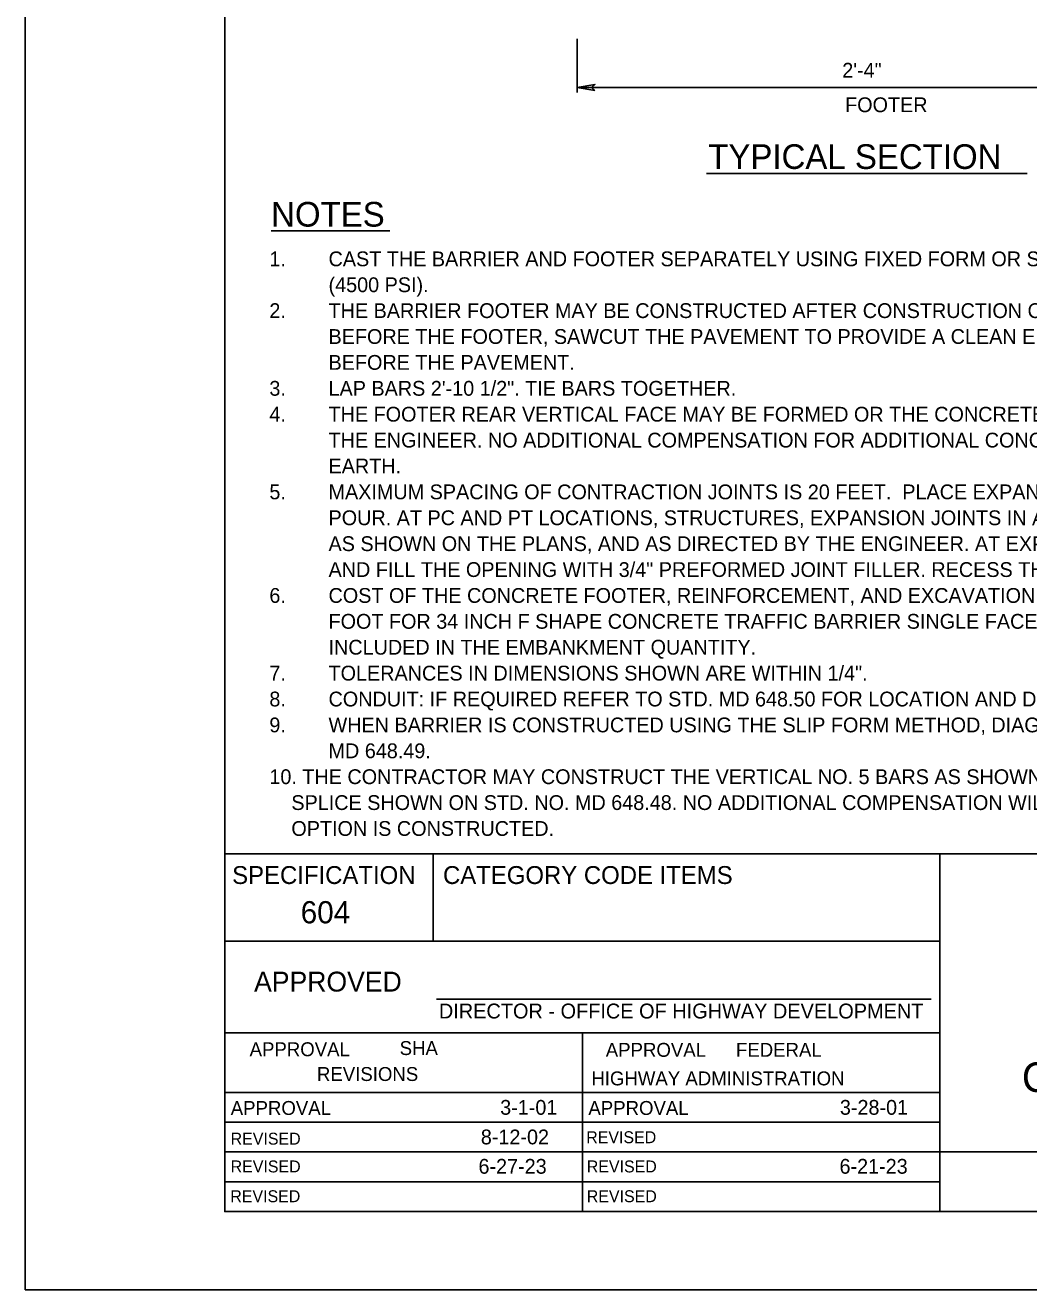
# Model space of a CAD drawing. Extents: x -32.9 to -15.8, y -6.5 to 4.5.
# Drawn here: x -24.32 to -20.25, y -6.5 to -1.37 of the extents above; entities that cross this region are included whole.
import ezdxf

# ---------------------------------------------------------------- set-up
doc = ezdxf.new("R2010")
doc.units = 0
for name, color, linetype in [('BORD-LINE', 7, 'Continuous'), ('DETL-DIMS', 7, 'Continuous'), ('Level 10', 7, 'Continuous'), ('Level 12', 7, 'Continuous'), ('Level 13', 7, 'Continuous'), ('TTLB-TEXT', 7, 'Continuous'), ('USER-CLIP', 7, 'Continuous')]:
    doc.layers.add(name, color=color, linetype=linetype)

msp = doc.modelspace()

# ---------------------------------------------------------------- linework, layer by layer
at = {"layer": 'BORD-LINE'}
for p, q in [((-20.6138, -4.729), (-23.5151, -4.729)), ((-22.6689, -5.0837), (-22.6689, -4.729)), ((-20.6138, -6.1798), (-20.6138, -4.729)), ((-16.1409, -4.729), (-20.6138, -4.729)), ((-23.5151, -5.0837), (-20.6138, -5.0837)), ((-22.6559, -5.3188), (-20.649, -5.3188)), ((-23.5151, -5.4544), (-22.6689, -5.4544)), ((-23.5151, -6.1798), (-23.5151, -5.4544)), ((-23.5151, -5.4544), (-20.6138, -5.4544)), ((-22.0644, -5.4544), (-22.0644, -6.1798)), ((-23.5151, -5.6962), (-20.6138, -5.6962)), ((-23.5151, -5.8171), (-20.6138, -5.8171)), ((-23.5151, -5.938), (-20.6138, -5.938)), ((-20.6138, -5.938), (-16.1409, -5.938)), ((-23.5151, -6.0589), (-20.6138, -6.0589)), ((-22.6689, -6.0589), (-20.6138, -6.0589))]:
    msp.add_line(p, q, dxfattribs=at)
msp.add_lwpolyline([(-23.5151, 4.1733), (-16.1409, 4.1733), (-16.1409, -6.1798), (-23.5151, -6.1798)], close=True, dxfattribs=at)
at = {"layer": 'DETL-DIMS'}
for p, q in [((-22.0848, -1.6207), (-22.0132, -1.608)), ((-22.0848, -1.6207), (-22.0133, -1.6332)), ((-22.0268, -1.6207), (-22.0132, -1.608)), ((-22.0133, -1.6332), (-22.0268, -1.6207))]:
    msp.add_line(p, q, dxfattribs=at)
msp.add_lwpolyline([(-22.0133, -1.6332), (-22.0848, -1.6207), (-22.0132, -1.608), (-22.0268, -1.6207)], close=True, dxfattribs=at)
at = {"layer": 'Level 10'}
for p, q in [((-22.0848, -1.4234), (-22.0848, -1.6415)), ((-19.752, -1.6207), (-22.0848, -1.6207))]:
    msp.add_line(p, q, dxfattribs=at)
at = {"layer": 'Level 12'}
msp.add_line((-21.5603, -1.9696), (-20.2595, -1.9696), dxfattribs=at)
at = {"layer": 'Level 13'}
msp.add_line((-23.3268, -2.2021), (-22.8451, -2.2021), dxfattribs=at)
at = {"layer": 'USER-CLIP'}
msp.add_lwpolyline([(-15.824, 4.5033), (-24.324, 4.5033), (-24.324, -6.4967), (-15.824, -6.4967)], close=True, dxfattribs=at)

# ---------------------------------------------------------------- texts
at = {"layer": 'Level 12'}
for s, height, p in [('2\'-4"', 0.06001, (-21.0101, -1.5807)), ('FOOTER', 0.06001, (-20.9986, -1.7207)), ('TYPICAL SECTION', 0.100016, (-21.5536, -1.951))]:
    msp.add_text(s, height=height, dxfattribs=at).set_placement(p)
at = {"layer": 'Level 13'}
for s, height, p in [('NOTES', 0.10002, (-23.3268, -2.1849)), ('1.', 0.06001, (-23.3339, -2.3457)), ('CAST THE BARRIER AND FOOTER SEPARATELY USING FIXED FORM OR SLIP FORM CONSTRUCTION WITH CONCRETE MIX NO.6 ', 0.0600095, (-23.0939, -2.3457)), ('(4500 PSI).', 0.06001, (-23.0939, -2.4507)), ('2.', 0.06001, (-23.3339, -2.5557)), ('THE BARRIER FOOTER MAY BE CONSTRUCTED AFTER CONSTRUCTION OF THE PAVEMENT. IF FLEXIBLE PAVEMENT IS CONSTRUCTED ', 0.0600095, (-23.0939, -2.5557)), ('BEFORE THE FOOTER, SAWCUT THE PAVEMENT TO PROVIDE A CLEAN EDGE. REMOVE FOOTER FORMS IF THE FOOTER IS CONSTRUCTED ', 0.0600095, (-23.0939, -2.6607)), ('BEFORE THE PAVEMENT.', 0.06001, (-23.0939, -2.7657)), ('3.', 0.06001, (-23.3339, -2.8708)), ('LAP BARS 2\'-10 1/2". TIE BARS TOGETHER.', 0.06001, (-23.0939, -2.8708)), ('4.', 0.06001, (-23.3339, -2.9758)), ('THE FOOTER REAR VERTICAL FACE MAY BE FORMED OR THE CONCRETE PLACED AGAINST THE VERTICAL EARTH SIDE IF APPROVED BY ', 0.0600095, (-23.0939, -2.9758)), ('THE ENGINEER. NO ADDITIONAL COMPENSATION FOR ADDITIONAL CONCRETE WILL BE PAID IF CONCRETE IS PLACED AGAINST THE ', 0.0600095, (-23.0939, -3.0808)), ('EARTH.', 0.06001, (-23.0939, -3.1858)), ('5.', 0.06001, (-23.3339, -3.2908)), ('MAXIMUM SPACING OF CONTRACTION JOINTS IS 20 FEET.  PLACE EXPANSION JOINTS IN THE BARRIER AND FOOTER AT THE END OF ', 0.0600095, (-23.0939, -3.2908)), ('POUR. AT PC AND PT LOCATIONS, STRUCTURES, EXPANSION JOINTS IN ABUTTING CONCRETE AND UNDERLYING CONCRETE. LOCATIONS ', 0.0600095, (-23.0939, -3.3958)), ('AS SHOWN ON THE PLANS, AND AS DIRECTED BY THE ENGINEER. AT EXPANSION JOINTS, SPACE BARRIER SECTIONS 3/4" APART', 0.0600095, (-23.0939, -3.5009)), ('AND FILL THE OPENING WITH 3/4" PREFORMED JOINT FILLER. RECESS THE FILLER 1/4" FROM THE FACE OF BARRIER.', 0.0600095, (-23.0939, -3.6059)), ('6.', 0.06001, (-23.3339, -3.7109)), ('COST OF THE CONCRETE FOOTER, REINFORCEMENT, AND EXCAVATION IS INCIDENTAL TO THE CONTRACT UNIT PRICE PER LINEAR ', 0.0600095, (-23.0939, -3.7109)), ('FOOT FOR 34 INCH F SHAPE CONCRETE TRAFFIC BARRIER SINGLE FACE TYPE 2. FILL MATERIAL IN BACK OF THE BARRIER IS ', 0.0600095, (-23.0939, -3.8159)), ('INCLUDED IN THE EMBANKMENT QUANTITY.', 0.06001, (-23.0939, -3.9209)), ('7.', 0.06001, (-23.3339, -4.0259)), ('TOLERANCES IN DIMENSIONS SHOWN ARE WITHIN 1/4".', 0.06001, (-23.0939, -4.0259)), ('8.', 0.06001, (-23.3339, -4.131)), ('CONDUIT: IF REQUIRED REFER TO STD. MD 648.50 FOR LOCATION AND DETAILS.', 0.06001, (-23.0939, -4.131)), ('9.', 0.06001, (-23.3339, -4.236)), ('WHEN BARRIER IS CONSTRUCTED USING THE SLIP FORM METHOD, DIAGONAL NO. 4 BARS ARE REQUIRED. SEE STD. ', 0.06001, (-23.0939, -4.236)), ('MD 648.49.', 0.06001, (-23.0939, -4.341)), ('10. THE CONTRACTOR MAY CONSTRUCT THE VERTICAL NO. 5 BARS AS SHOWN ON THIS STANDARD OR USE THE LAP', 0.06001, (-23.3339, -4.446)), ('    SPLICE SHOWN ON STD. NO. MD 648.48. NO ADDITIONAL COMPENSATION WILL BE MADE FOR WHICHEVER', 0.06001, (-23.3339, -4.551)), ('    OPTION IS CONSTRUCTED.', 0.06001, (-23.3339, -4.656)), ('604', 0.09001, (-23.2068, -5.0107)), ('CONCRETE TRAFFIC BARRIER SINGLE FACE', 0.120019, (-20.2815, -5.6946)), ('3-1-01', 0.06, (-22.3977, -5.7871)), ('3-28-01', 0.06, (-21.0198, -5.7871)), ('8-12-02', 0.06, (-22.4762, -5.9071)), ('6-27-23', 0.06, (-22.4857, -6.0262)), ('6-21-23', 0.06, (-21.0213, -6.0262))]:
    msp.add_text(s, height=height, dxfattribs=at).set_placement(p)
at = {"layer": 'TTLB-TEXT'}
for s, height, p in [('SPECIFICATION', 0.07254, (-23.4849, -4.8511)), ('CATEGORY CODE ITEMS ', 0.07254, (-22.6296, -4.8511)), ('APPROVED', 0.0806, (-23.3959, -5.2874)), ('DIRECTOR - OFFICE OF HIGHWAY DEVELOPMENT', 0.0604, (-22.6464, -5.3966)), ('APPROVAL', 0.05642, (-23.4141, -5.5496)), ('SHA', 0.05642, (-22.8055, -5.5449)), ('APPROVAL', 0.05642, (-21.9695, -5.5521)), ('FEDERAL', 0.05642, (-21.4414, -5.552)), ('REVISIONS', 0.05642, (-23.141, -5.6501)), ('HIGHWAY ADMINISTRATION', 0.05642, (-22.028, -5.6678)), ('APPROVAL', 0.05642, (-23.4907, -5.7878)), ('APPROVAL', 0.05642, (-22.04, -5.7878)), ('REVISED', 0.04836, (-23.491, -5.9083)), ('REVISED', 0.04836, (-22.0487, -5.9024)), ('REVISED', 0.04836, (-23.491, -6.0209)), ('REVISED', 0.04836, (-22.0464, -6.0209)), ('REVISED', 0.04836, (-23.4923, -6.1417)), ('REVISED', 0.04836, (-22.0464, -6.1417))]:
    msp.add_text(s, height=height, dxfattribs=at).set_placement(p)

doc.saveas('drawing.dxf')
